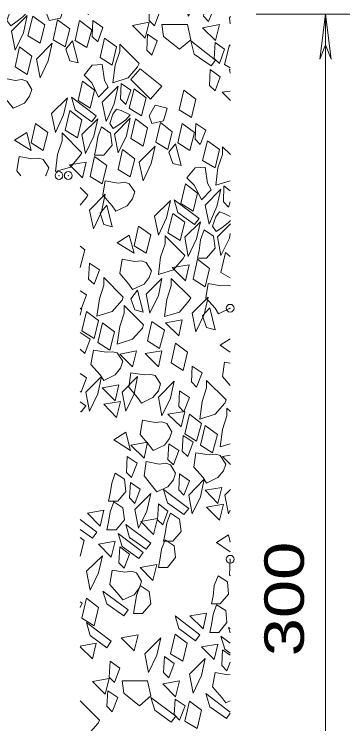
# Model space of a CAD drawing. Extents: x 312583 to 312854, y 144419 to 144597.
# Drawn here: x 312777.68 to 312784.13, y 144501.24 to 144514.89 of the extents above; entities that cross this region are included whole.
import ezdxf

# ---------------------------------------------------------------- set-up
doc = ezdxf.new("R2010")
doc.units = 0
doc.header["$LTSCALE"] = 0.3
doc.header["$PDMODE"] = 32
doc.header["$PDSIZE"] = 0.15
doc.layers.add('2', color=7, linetype='Continuous', lineweight=13)

msp = doc.modelspace()

# ---------------------------------------------------------------- linework, layer by layer
at = {"layer": '2'}
for p, q in [((312781.8142, 144514.8239), (312781.8372, 144514.8469)), ((312781.8295, 144514.7089), (312781.8142, 144514.8239)), ((312782.3279, 144514.8929), (312784.1295, 144514.8929)), ((312783.6619, 144514.8929), (312783.5545, 144514.0266)), ((312783.6619, 144491.7856), (312783.6619, 144514.8929)), ((312783.6619, 144514.8929), (312783.7692, 144514.0266)), ((312783.5545, 144514.0266), (312783.6619, 144514.3026)), ((312783.7692, 144514.0266), (312783.6619, 144514.3026)), ((312781.8295, 144513.8579), (312781.7222, 144513.9269)), ((312781.8295, 144513.4132), (312781.6762, 144513.3902)), ((312781.6762, 144513.3902), (312781.8372, 144513.2292)), ((312778.5405, 144511.7879), (312778.5405, 144511.7802)), ((312778.7245, 144511.7879), (312778.7169, 144511.7879)), ((312781.8295, 144511.4966), (312781.7069, 144511.5886)), ((312781.8295, 144510.9982), (312781.7145, 144511.0596)), ((312781.5842, 144510.6072), (312781.8372, 144510.8602)), ((312781.8295, 144509.8176), (312781.6532, 144509.9249)), ((312781.8295, 144508.6446), (312781.6379, 144508.5219)), ((312781.6379, 144508.5219), (312781.8295, 144508.3916)), ((312781.8295, 144506.4059), (312781.6839, 144506.3829)), ((312781.6839, 144506.3829), (312781.8372, 144506.2296)), ((312781.7299, 144505.6392), (312781.8372, 144505.7466)), ((312781.5689, 144504.7269), (312781.8295, 144504.5506)), ((312781.8295, 144502.5572), (312781.6839, 144502.6646)), ((312781.7299, 144502.6722), (312781.8295, 144502.5956))]:
    msp.add_line(p, q, dxfattribs=at)
for points in [[(312777.5822, 144514.8929), (312777.5362, 144514.7702), (312777.6129, 144514.6706), (312777.7125, 144514.7396), (312777.8429, 144514.8392), (312777.8965, 144514.8929)], [(312778.3029, 144514.8929), (312778.3489, 144514.7702), (312778.5712, 144514.8162), (312778.5942, 144514.8929)], [(312779.1079, 144514.8929), (312779.1079, 144514.8852), (312779.0925, 144514.8929)], [(312780.2732, 144514.8929), (312780.2732, 144514.7702), (312780.3729, 144514.6706), (312780.4572, 144514.8929)], [(312781.0475, 144514.8929), (312781.0245, 144514.8546), (312781.0169, 144514.8929)], [(312781.3235, 144514.8929), (312781.3159, 144514.8546), (312781.4155, 144514.7549), (312781.4692, 144514.8929)], [(312781.7222, 144513.9269), (312781.8142, 144514.3026), (312781.8295, 144514.2872)], [(312781.8295, 144513.8196), (312781.8142, 144513.8349), (312781.8295, 144513.7582)], [(312781.8372, 144512.1942), (312781.6839, 144512.3399), (312781.6839, 144512.1942)], [(312781.6839, 144512.1942), (312781.5919, 144511.9336), (312781.5535, 144511.6039), (312781.8295, 144511.6882)], [(312778.2799, 144511.7802), (312778.2952, 144511.8032), (312778.3412, 144511.9336), (312778.2339, 144512.0946), (312778.1495, 144512.1252), (312778.0192, 144512.1099), (312777.7739, 144512.1559), (312777.7279, 144511.8799), (312777.8045, 144511.7802)], [(312778.9469, 144511.2206), (312779.0619, 144511.3586), (312779.0925, 144511.4122), (312778.9469, 144511.5579)], [(312781.7069, 144511.5886), (312781.6992, 144511.2819), (312781.7989, 144511.1822), (312781.8295, 144511.2819)], [(312781.7145, 144511.0596), (312781.6225, 144511.0902), (312781.5535, 144510.9906), (312781.4922, 144510.8142), (312781.5612, 144510.7146), (312781.6685, 144510.7836), (312781.7989, 144510.8832), (312781.8372, 144510.9216)], [(312781.8295, 144510.6762), (312781.8142, 144510.5842), (312781.6532, 144510.2469), (312781.5842, 144510.6072)], [(312778.9469, 144510.4309), (312779.0389, 144510.3619), (312778.9469, 144510.0169)], [(312781.6532, 144509.9249), (312781.7375, 144510.3082), (312781.8295, 144510.2316)], [(312781.8372, 144509.6642), (312781.7835, 144509.6796), (312781.6532, 144509.6642), (312781.4079, 144509.7102), (312781.3619, 144509.4342), (312781.5382, 144509.2349)], [(312778.9469, 144509.2349), (312778.9622, 144509.2196), (312779.0695, 144509.4956), (312778.9469, 144509.5722)], [(312778.9469, 144509.1046), (312778.9775, 144509.2272), (312778.9469, 144509.2272)], [(312781.5382, 144509.2349), (312781.6072, 144509.1276), (312781.8295, 144509.2349)], [(312778.9469, 144508.4452), (312779.0389, 144508.3609), (312779.1385, 144508.6369), (312778.9469, 144508.7672)], [(312781.8295, 144508.1769), (312781.7222, 144508.1999), (312781.6839, 144507.9239), (312781.8295, 144507.7476)], [(312778.9469, 144507.6326), (312778.9622, 144507.6172), (312779.0695, 144507.8932), (312778.9469, 144507.9776)], [(312778.9469, 144507.2492), (312778.9622, 144507.2416), (312779.0542, 144507.3566), (312778.9469, 144507.4332)], [(312781.8372, 144507.2492), (312781.7682, 144507.3106), (312781.7682, 144507.1649)], [(312781.7682, 144507.1649), (312781.6839, 144506.9042), (312781.6379, 144506.5669), (312781.8295, 144506.6282)], [(312781.8295, 144505.3479), (312781.7989, 144505.2789), (312781.7299, 144505.6392)], [(312778.9469, 144504.9799), (312779.1845, 144504.8112), (312779.2689, 144504.9262), (312778.9469, 144505.1716)], [(312778.9469, 144504.8266), (312779.0235, 144504.7652), (312778.9469, 144504.4662)], [(312781.8295, 144504.7346), (312781.7989, 144504.8726), (312781.5689, 144504.7269)], [(312781.8295, 144504.4049), (312781.8142, 144504.0982), (312781.8372, 144504.0829)], [(312778.9469, 144503.4772), (312778.9852, 144503.5616), (312778.9469, 144503.5846)], [(312781.8295, 144503.0709), (312781.7989, 144503.0939), (312781.8295, 144502.9866)], [(312781.8295, 144502.7872), (312781.6532, 144502.9252), (312781.7299, 144502.6722)], [(312778.9469, 144502.7182), (312779.1845, 144502.4882), (312779.2535, 144502.7872), (312778.9469, 144502.7336)], [(312781.6839, 144502.6646), (312781.6685, 144502.3579), (312781.7682, 144502.2582), (312781.8295, 144502.4269)], [(312781.8295, 144502.1892), (312781.7835, 144502.1816), (312781.5382, 144502.2276), (312781.4922, 144501.9516), (312781.6685, 144501.7446)], [(312781.8295, 144501.4609), (312781.3619, 144501.8212), (312781.4385, 144501.5682)], [(312778.9469, 144500.9932), (312779.1002, 144501.0316), (312779.2919, 144501.2539), (312779.3149, 144501.3076), (312778.9469, 144501.6832)], [(312781.6685, 144501.7446), (312781.7452, 144501.6449), (312781.8295, 144501.6832)], [(312781.4385, 144501.5682), (312781.7605, 144501.3382), (312781.8295, 144501.4456)]]:
    msp.add_lwpolyline(points, dxfattribs=at)
for points in [[(312777.6282, 144514.5632), (312777.9272, 144514.8699), (312777.8582, 144514.5326), (312777.6972, 144514.2029)], [(312777.9425, 144514.4789), (312778.0345, 144514.8546), (312778.2645, 144514.6859), (312778.1802, 144514.3332)], [(312778.4255, 144514.4022), (312778.5099, 144514.7856), (312778.7475, 144514.6092), (312778.6555, 144514.2642)], [(312778.8472, 144514.3869), (312778.9315, 144514.7702), (312779.1692, 144514.5939), (312779.0772, 144514.2489)], [(312779.1922, 144514.7702), (312779.1769, 144514.4636), (312779.2842, 144514.3639), (312779.3839, 144514.6399)], [(312779.9512, 144514.6782), (312780.1965, 144514.4329), (312780.2732, 144514.7396)], [(312780.5492, 144514.4636), (312780.8559, 144514.2182), (312781.0705, 144514.4022), (312781.0092, 144514.6936), (312780.5185, 144514.6936)], [(312781.3005, 144514.6322), (312781.5459, 144514.3869), (312781.6225, 144514.6936)], [(312780.2425, 144514.5096), (312780.2272, 144514.2029), (312780.3269, 144514.1032), (312780.4265, 144514.3792)], [(312778.6709, 144514.2182), (312778.7475, 144513.9959), (312778.9085, 144513.9576), (312778.8012, 144514.3792)], [(312779.3302, 144514.0572), (312779.4145, 144514.4329), (312779.6445, 144514.2642), (312779.5602, 144513.9116)], [(312781.1395, 144514.1262), (312781.4615, 144513.8962), (312781.5459, 144514.0112), (312781.0705, 144514.3792)], [(312777.6972, 144513.8809), (312777.7815, 144514.2642), (312778.0192, 144514.0879), (312777.9272, 144513.7352)], [(312778.1035, 144514.0266), (312778.4102, 144514.3332), (312778.3335, 144513.9959), (312778.1802, 144513.6662)], [(312779.7059, 144514.1722), (312779.6215, 144513.9116), (312779.5755, 144513.5742), (312779.8669, 144513.6662), (312780.0509, 144513.8809), (312780.0815, 144513.9422), (312779.7059, 144514.3179)], [(312781.5382, 144514.3486), (312781.5229, 144514.0419), (312781.6225, 144513.9422), (312781.7222, 144514.2182)], [(312779.2995, 144513.2982), (312779.1692, 144513.5742), (312779.0235, 144513.7199), (312779.1769, 144513.9116), (312779.3685, 144513.9269), (312779.4145, 144513.6202), (312779.4835, 144513.4899)], [(312780.0969, 144513.8426), (312779.9205, 144513.6356), (312780.2962, 144513.2599), (312780.5185, 144513.5052)], [(312781.4462, 144513.8272), (312781.4309, 144513.5206), (312781.5382, 144513.4209), (312781.6379, 144513.6892)], [(312777.5822, 144513.1832), (312777.6589, 144513.0836), (312777.8735, 144513.1832), (312777.9732, 144513.3136), (312778.0192, 144513.4439), (312777.9195, 144513.6049), (312777.8275, 144513.6356), (312777.6972, 144513.6202), (312777.4519, 144513.6662), (312777.4059, 144513.3902)], [(312778.9085, 144513.2292), (312778.9929, 144513.6049), (312779.2229, 144513.4286), (312779.1385, 144513.0836)], [(312779.7365, 144513.5589), (312779.7212, 144513.2599), (312779.8209, 144513.1526), (312779.9205, 144513.4286)], [(312779.3685, 144513.1986), (312779.6752, 144513.5052), (312779.5985, 144513.1679), (312779.4452, 144512.8306)], [(312779.8899, 144513.0836), (312779.9819, 144513.4592), (312780.2119, 144513.2829), (312780.1275, 144512.9379)], [(312780.8482, 144513.0529), (312780.9402, 144513.4286), (312781.1702, 144513.2599), (312781.0859, 144512.9072)], [(312778.3949, 144512.9839), (312778.7015, 144513.2829), (312778.6249, 144512.9532), (312778.4715, 144512.6159)], [(312778.8472, 144513.0529), (312779.1692, 144512.8229), (312779.2535, 144512.9379), (312778.7782, 144513.2982)], [(312780.3882, 144513.1449), (312780.2732, 144512.9379), (312780.3269, 144512.7922), (312780.5492, 144512.8382), (312780.6182, 144513.0836)], [(312778.6555, 144512.6619), (312778.7475, 144513.0376), (312778.9775, 144512.8612), (312778.8932, 144512.5162)], [(312779.7365, 144513.0376), (312779.6445, 144513.0682), (312779.5755, 144512.9686), (312779.5142, 144512.7922), (312779.5832, 144512.6926), (312779.6905, 144512.7616), (312779.8209, 144512.8612), (312779.9052, 144512.9532)], [(312778.9775, 144512.5776), (312779.2842, 144512.8766), (312779.2075, 144512.5469), (312779.0465, 144512.2096)], [(312779.6062, 144512.5852), (312779.9052, 144512.8919), (312779.8362, 144512.5546), (312779.6752, 144512.2249)], [(312779.9205, 144512.5009), (312780.0125, 144512.8766), (312780.2425, 144512.7079), (312780.1582, 144512.3552)], [(312778.0039, 144512.4166), (312778.0882, 144512.7922), (312778.3259, 144512.6159), (312778.2339, 144512.2709)], [(312780.4035, 144512.4319), (312780.4879, 144512.8076), (312780.7179, 144512.6312), (312780.6335, 144512.2862)], [(312780.8252, 144512.4166), (312780.9095, 144512.7922), (312781.1472, 144512.6159), (312781.0552, 144512.2709)], [(312781.1702, 144512.7922), (312781.1549, 144512.4856), (312781.2545, 144512.3859), (312781.3619, 144512.6619)], [(312777.6819, 144512.4702), (312778.0039, 144512.2709), (312777.9195, 144512.6159)], [(312778.6019, 144512.4549), (312778.5099, 144512.1942), (312778.4715, 144511.8646), (312778.7629, 144511.9489), (312778.9469, 144512.1712), (312778.9775, 144512.2249), (312778.6019, 144512.6082)], [(312779.3532, 144512.7232), (312779.2842, 144512.5316), (312779.2535, 144512.3246), (312779.2229, 144512.1789), (312779.3992, 144512.1789), (312779.5602, 144512.3706), (312779.5295, 144512.6006)], [(312781.3005, 144512.0792), (312781.3925, 144512.4549), (312781.6225, 144512.2862), (312781.5382, 144511.9336)], [(312780.0815, 144512.0486), (312780.3882, 144512.3552), (312780.3115, 144512.0179), (312780.1582, 144511.6882)], [(312780.6489, 144512.2402), (312780.7255, 144512.0179), (312780.8865, 144511.9796), (312780.7792, 144512.4012)], [(312779.6752, 144511.9029), (312779.7595, 144512.2862), (312779.9972, 144512.1099), (312779.9052, 144511.7649)], [(312778.7399, 144511.9949), (312778.9469, 144511.7879), (312778.9929, 144511.7419), (312779.0619, 144512.0486)], [(312779.1385, 144511.7726), (312779.2229, 144512.1559), (312779.4605, 144511.9796), (312779.3685, 144511.6269)], [(312781.2775, 144511.3202), (312781.1472, 144511.5962), (312780.9939, 144511.7419), (312781.1549, 144511.9336), (312781.3465, 144511.9489), (312781.3925, 144511.6422), (312781.4615, 144511.5119)], [(312779.5602, 144511.2052), (312779.6292, 144511.1056), (312779.8515, 144511.2052), (312779.9512, 144511.3432), (312779.9972, 144511.4736), (312779.8899, 144511.6269), (312779.8055, 144511.6576), (312779.6752, 144511.6422), (312779.4299, 144511.6882), (312779.3839, 144511.4122)], [(312780.8789, 144511.2512), (312780.9709, 144511.6269), (312781.2009, 144511.4506), (312781.1165, 144511.1056)], [(312781.3465, 144511.2206), (312781.6532, 144511.5272), (312781.5765, 144511.1899), (312781.4232, 144510.8526)], [(312779.1232, 144511.1209), (312779.4299, 144511.4276), (312779.3532, 144511.0902), (312779.1999, 144510.7606)], [(312780.3729, 144511.0059), (312780.6795, 144511.3049), (312780.6029, 144510.9752), (312780.4495, 144510.6379)], [(312780.8252, 144511.0749), (312781.1472, 144510.8449), (312781.2315, 144510.9599), (312780.7562, 144511.3202)], [(312779.3302, 144511.0672), (312779.3992, 144510.8449), (312779.5602, 144510.7989), (312779.4605, 144511.2206)], [(312780.6335, 144510.6839), (312780.7255, 144511.0596), (312780.9555, 144510.8909), (312780.8712, 144510.5382)], [(312779.9819, 144510.4386), (312780.0662, 144510.8142), (312780.3039, 144510.6456), (312780.2119, 144510.2929)], [(312780.9555, 144510.5996), (312781.2622, 144510.8986), (312781.1855, 144510.5689), (312781.0245, 144510.2316)], [(312781.3312, 144510.7452), (312781.2622, 144510.5536), (312781.2315, 144510.3466), (312781.2009, 144510.2009), (312781.3772, 144510.2009), (312781.5382, 144510.3926), (312781.5075, 144510.6226)], [(312779.6599, 144510.4922), (312779.9819, 144510.2929), (312779.8899, 144510.6379)], [(312780.5799, 144510.4769), (312780.4879, 144510.2162), (312780.4495, 144509.8866), (312780.7409, 144509.9709), (312780.9249, 144510.1932), (312780.9555, 144510.2469), (312780.5799, 144510.6302)], [(312779.8822, 144509.6949), (312779.9512, 144509.5952), (312780.1735, 144509.6949), (312780.2732, 144509.8252), (312780.3192, 144509.9556), (312780.2119, 144510.1166), (312780.1275, 144510.1472), (312779.9972, 144510.1319), (312779.7519, 144510.1779), (312779.7059, 144509.9019)], [(312781.1165, 144509.7946), (312781.2009, 144510.1779), (312781.4309, 144510.0016), (312781.3465, 144509.6489)], [(312779.1232, 144510.1012), (312779.1079, 144509.7946), (312779.2152, 144509.6949), (312779.3149, 144509.9709)], [(312780.7179, 144510.0169), (312780.9709, 144509.7639), (312781.0399, 144510.0706)], [(312779.3992, 144509.6796), (312779.3149, 144509.4189), (312779.2689, 144509.0816), (312779.5602, 144509.1736), (312779.7519, 144509.3882), (312779.7749, 144509.4496), (312779.3992, 144509.8252)], [(312780.2119, 144509.5032), (312780.5185, 144509.8099), (312780.4495, 144509.4802), (312780.2885, 144509.1429)], [(312780.6949, 144509.6642), (312780.6105, 144509.4036), (312780.5645, 144509.0739), (312780.8559, 144509.1582), (312781.0399, 144509.3806), (312781.0705, 144509.4342), (312780.6949, 144509.8099)], [(312779.9205, 144509.4189), (312779.9972, 144509.2042), (312780.1582, 144509.1582), (312780.0509, 144509.5799)], [(312781.1012, 144509.1429), (312781.4079, 144509.4496), (312781.3312, 144509.1122), (312781.1702, 144508.7826)], [(312779.7902, 144509.1429), (312779.7059, 144508.8822), (312779.6599, 144508.5449), (312779.9512, 144508.6369), (312780.1429, 144508.8516), (312780.1659, 144508.9129), (312779.7902, 144509.2886)], [(312781.3005, 144509.0892), (312781.3772, 144508.8669), (312781.5382, 144508.8209), (312781.4385, 144509.2426)], [(312778.9775, 144508.7979), (312779.0695, 144509.1736), (312779.2995, 144508.9972), (312779.2152, 144508.6522)], [(312779.2842, 144508.5756), (312779.3762, 144508.9512), (312779.6062, 144508.7826), (312779.5142, 144508.4299)], [(312780.2425, 144508.6062), (312780.3269, 144508.9819), (312780.5645, 144508.8132), (312780.4725, 144508.4606)], [(312780.5875, 144508.9512), (312780.8405, 144508.7059), (312780.9095, 144509.0126)], [(312780.6949, 144508.1846), (312780.7792, 144508.5602), (312781.0092, 144508.3916), (312780.9249, 144508.0389)], [(312779.3302, 144507.9546), (312779.3992, 144507.8472), (312779.6215, 144507.9546), (312779.7212, 144508.0849), (312779.7672, 144508.2152), (312779.6599, 144508.3762), (312779.5755, 144508.3992), (312779.4452, 144508.3916), (312779.1999, 144508.4299), (312779.1539, 144508.1539)], [(312779.7059, 144508.3532), (312779.9512, 144508.1079), (312780.0279, 144508.4146)], [(312780.1965, 144508.3609), (312780.4495, 144508.1079), (312780.5185, 144508.4146)], [(312781.1012, 144508.1232), (312781.0859, 144507.8166), (312781.1855, 144507.7169), (312781.2929, 144507.9929)], [(312780.0509, 144507.5176), (312780.1275, 144507.4102), (312780.3422, 144507.5176), (312780.4495, 144507.6479), (312780.4879, 144507.7782), (312780.3882, 144507.9392), (312780.3039, 144507.9622), (312780.1735, 144507.9546), (312779.9205, 144507.9929), (312779.8822, 144507.7169)], [(312779.0542, 144507.6172), (312779.3532, 144507.9239), (312779.2842, 144507.5866), (312779.1232, 144507.2569)], [(312779.7519, 144507.6172), (312780.0509, 144507.9239), (312779.9819, 144507.5866), (312779.8209, 144507.2569)], [(312780.4495, 144507.5252), (312780.7562, 144507.8319), (312780.6795, 144507.5022), (312780.5185, 144507.1649)], [(312781.3772, 144507.7016), (312781.2929, 144507.4409), (312781.2469, 144507.1036), (312781.5382, 144507.1956), (312781.7299, 144507.4102), (312781.7529, 144507.4716), (312781.3772, 144507.8472)], [(312779.3685, 144507.7016), (312779.6215, 144507.4562), (312779.6905, 144507.7629)], [(312780.8559, 144507.6479), (312780.8405, 144507.3412), (312780.9402, 144507.2416), (312781.0475, 144507.5176)], [(312779.3992, 144507.3872), (312779.6445, 144507.1342), (312779.7212, 144507.4409)], [(312780.6335, 144507.1956), (312780.8865, 144506.9502), (312780.9555, 144507.2492)], [(312780.9555, 144506.8199), (312781.0475, 144507.1956), (312781.2775, 144507.0192), (312781.1855, 144506.6742)], [(312780.2732, 144506.5976), (312780.3499, 144506.4979), (312780.5645, 144506.5976), (312780.6642, 144506.7279), (312780.7102, 144506.8582), (312780.6105, 144507.0192), (312780.5185, 144507.0499), (312780.3882, 144507.0346), (312780.1429, 144507.0806), (312780.0969, 144506.8046)], [(312781.2622, 144506.5976), (312781.3465, 144506.9809), (312781.5842, 144506.8046), (312781.4922, 144506.4519)], [(312779.5909, 144506.7049), (312779.9129, 144506.4979), (312779.8209, 144506.8506)], [(312780.9249, 144506.7892), (312780.9095, 144506.4826), (312781.0169, 144506.3829), (312781.1165, 144506.6589)], [(312779.9205, 144506.5976), (312780.1735, 144506.3522), (312780.2425, 144506.6589)], [(312780.6489, 144506.6282), (312780.6335, 144506.3216), (312780.7409, 144506.2219), (312780.8405, 144506.4979)], [(312781.3082, 144505.9766), (312781.3772, 144505.8692), (312781.5919, 144505.9766), (312781.6992, 144506.1069), (312781.7452, 144506.2372), (312781.6379, 144506.3982), (312781.5535, 144506.4289), (312781.4232, 144506.4136), (312781.1702, 144506.4519), (312781.1319, 144506.1759)], [(312779.8515, 144506.3829), (312779.8362, 144506.0762), (312779.9359, 144505.9766), (312780.0432, 144506.2526)], [(312780.3422, 144505.8002), (312780.4189, 144505.7006), (312780.6335, 144505.8002), (312780.7409, 144505.9306), (312780.7792, 144506.0609), (312780.6795, 144506.2219), (312780.5952, 144506.2526), (312780.4649, 144506.2372), (312780.2119, 144506.2832), (312780.1735, 144506.0072)], [(312779.6215, 144506.0609), (312779.5525, 144505.8692), (312779.5219, 144505.6699), (312779.4912, 144505.5242), (312779.6675, 144505.5242), (312779.8209, 144505.7082), (312779.7979, 144505.9459)], [(312780.8559, 144506.0456), (312780.8405, 144505.7389), (312780.9402, 144505.6392), (312781.0475, 144505.9152)], [(312781.0322, 144505.6392), (312781.3312, 144505.9459), (312781.2622, 144505.6086), (312781.1012, 144505.2789)], [(312779.9129, 144505.8846), (312779.8975, 144505.5856), (312779.9972, 144505.4782), (312780.0969, 144505.7542)], [(312781.3465, 144505.7312), (312781.5919, 144505.4782), (312781.6685, 144505.7849)], [(312779.9972, 144505.3632), (312780.3039, 144505.6699), (312780.2272, 144505.3326), (312780.0662, 144505.0029)], [(312780.6259, 144505.4936), (312780.9402, 144505.2636), (312781.0322, 144505.3786), (312780.5492, 144505.7466)], [(312779.5909, 144505.5089), (312779.5219, 144505.3172), (312779.4912, 144505.1179), (312779.4605, 144504.9722), (312779.6369, 144504.9722), (312779.7979, 144505.1639), (312779.7672, 144505.3939)], [(312780.4495, 144505.4706), (312780.4342, 144505.1639), (312780.5339, 144505.0642), (312780.6335, 144505.3326)], [(312781.3772, 144505.4092), (312781.6225, 144505.1562), (312781.6992, 144505.4629)], [(312779.0849, 144505.2942), (312779.3302, 144505.0412), (312779.3992, 144505.3479)], [(312780.6795, 144505.2942), (312780.6105, 144505.1026), (312780.5799, 144504.9032), (312780.5492, 144504.7499), (312780.7255, 144504.7499), (312780.8865, 144504.9416), (312780.8559, 144505.1792)], [(312780.1122, 144505.1332), (312780.3575, 144504.8802), (312780.4342, 144505.1869)], [(312779.8975, 144504.8266), (312780.2119, 144504.5966), (312780.3039, 144504.7116), (312779.8209, 144505.0719)], [(312779.7519, 144504.6502), (312780.0739, 144504.4202), (312780.1582, 144504.5352), (312779.6752, 144504.9032)], [(312779.2995, 144504.6962), (312779.5449, 144504.4432), (312779.6215, 144504.7499)], [(312780.5799, 144504.7806), (312780.5109, 144504.5966), (312780.4802, 144504.3896), (312780.4495, 144504.2439), (312780.6259, 144504.2439), (312780.7792, 144504.4356), (312780.7562, 144504.6656)], [(312779.7059, 144504.6426), (312779.6905, 144504.3359), (312779.7902, 144504.2362), (312779.8975, 144504.5046)], [(312779.0695, 144504.1749), (312779.3762, 144504.4739), (312779.2995, 144504.1442), (312779.1385, 144503.8069)], [(312780.0969, 144504.2439), (312780.3422, 144503.9986), (312780.4189, 144504.3052)], [(312779.6905, 144503.7226), (312779.7672, 144503.6229), (312779.9819, 144503.7226), (312780.0892, 144503.8529), (312780.1275, 144503.9832), (312780.0279, 144504.1442), (312779.9359, 144504.1749), (312779.8055, 144504.1596), (312779.5602, 144504.1979), (312779.5142, 144503.9219)], [(312781.5995, 144504.0829), (312781.5229, 144503.8989), (312781.4999, 144503.6919), (312781.4692, 144503.5462), (312781.6379, 144503.5462), (312781.7989, 144503.7302), (312781.7759, 144503.9679)], [(312780.0969, 144503.8989), (312780.0279, 144503.7072), (312779.9972, 144503.5079), (312779.9742, 144503.3622), (312780.1429, 144503.3622), (312780.3039, 144503.5462), (312780.2732, 144503.7839)], [(312779.4605, 144503.5462), (312779.7825, 144503.3162), (312779.8669, 144503.4312), (312779.3839, 144503.7916)], [(312778.9775, 144503.2702), (312779.0695, 144503.6536), (312779.2995, 144503.4772), (312779.2152, 144503.1246)], [(312781.5689, 144503.5309), (312781.4999, 144503.3392), (312781.4692, 144503.1399), (312781.4385, 144502.9942), (312781.6149, 144502.9942), (312781.7682, 144503.1859), (312781.7452, 144503.4159)], [(312780.8405, 144503.0709), (312781.1625, 144502.8332), (312781.2469, 144502.9482), (312780.7715, 144503.3162)], [(312781.0552, 144503.3162), (312781.3082, 144503.0632), (312781.3772, 144503.3699)], [(312779.1385, 144502.9406), (312779.4605, 144502.7029), (312779.5449, 144502.8256), (312779.0695, 144503.1859)], [(312779.7365, 144502.8946), (312779.9819, 144502.6416), (312780.0585, 144502.9482)], [(312780.1889, 144502.5879), (312780.4955, 144502.8946), (312780.4189, 144502.5572), (312780.2579, 144502.2276)], [(312780.6795, 144502.5879), (312780.7715, 144502.9636), (312781.0015, 144502.7872), (312780.9172, 144502.4422)], [(312781.2775, 144502.7182), (312781.5229, 144502.4729), (312781.5919, 144502.7719)], [(312780.5645, 144502.5342), (312780.5492, 144502.2276), (312780.6489, 144502.1202), (312780.7562, 144502.3962)], [(312781.0475, 144502.1969), (312781.3465, 144502.4959), (312781.2775, 144502.1662), (312781.1165, 144501.8289)], [(312779.5219, 144502.4422), (312779.5065, 144502.1356), (312779.6062, 144502.0359), (312779.7059, 144502.3119)], [(312779.1845, 144502.0512), (312779.4299, 144501.8059), (312779.5065, 144502.1126)], [(312779.7825, 144501.8289), (312780.0892, 144501.5836), (312780.3039, 144501.7752), (312780.2425, 144502.0666), (312779.7519, 144502.0666)], [(312780.5339, 144502.0052), (312780.7792, 144501.7599), (312780.8559, 144502.0666)], [(312779.4759, 144501.8749), (312779.4605, 144501.5759), (312779.5602, 144501.4686), (312779.6675, 144501.7446)], [(312780.3805, 144501.4992), (312780.6949, 144501.2692), (312780.7869, 144501.3842), (312780.3039, 144501.7446)], [(312780.7715, 144501.7139), (312780.7562, 144501.4149), (312780.8559, 144501.3076), (312780.9632, 144501.5836)], [(312780.9555, 144501.2922), (312781.0475, 144501.6756), (312781.2775, 144501.4992), (312781.1932, 144501.1466)]]:
    msp.add_lwpolyline(points, close=True, dxfattribs=at)
for p in [(312778.5405, 144511.7879), (312778.7169, 144511.7879), (312781.8295, 144509.2349), (312781.8295, 144504.4049)]:
    msp.add_point(p, dxfattribs=at)

# ---------------------------------------------------------------- texts
at = {"layer": '2', "width": 1.3}
msp.add_text('300 ', height=0.76, rotation=90, dxfattribs=at).set_placement((312783.2476, 144502.5382))

doc.saveas('drawing.dxf')
